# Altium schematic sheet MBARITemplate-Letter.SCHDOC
size Letter; Organization: Monterey Bay Aquarium Research Institute; Address1: 7700 Sandholdt Rd; Address2: Moss Landing, CA 95039-9644; CompanyName: MBARI
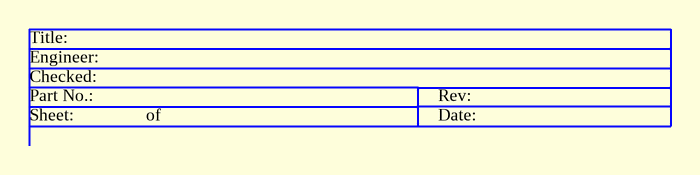
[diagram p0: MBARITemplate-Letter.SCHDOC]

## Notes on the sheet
- Sheet:
- Title:
- Engineer:
- Part No.:
- Checked:
- of
- Rev:
- Date:
